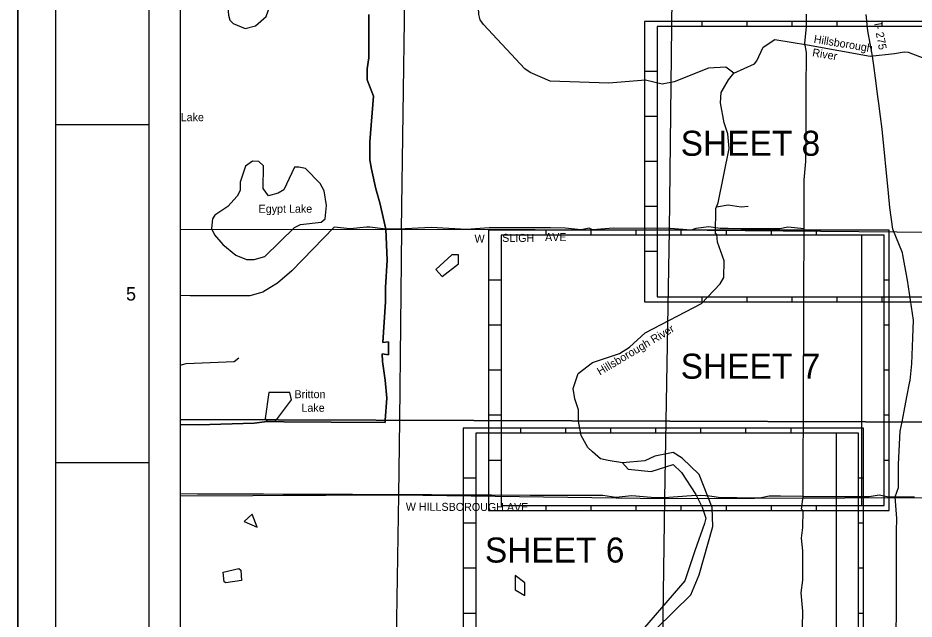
# Model space of a CAD drawing. Extents: x 492225 to 553725, y 1303773 to 1347273.
# Drawn here: x 492225 to 510130, y 1329150 to 1341161 of the extents above; entities that cross this region are included whole.
import ezdxf

# ---------------------------------------------------------------- set-up
doc = ezdxf.new("R2010")
doc.units = 0
for name, color, linetype in [('G-ANNO-TTLB', 7, 'Continuous'), ('Level 1', 7, 'Continuous'), ('Level 13', 7, 'Continuous'), ('Level 19', 7, 'Continuous'), ('Level 22', 7, 'Continuous'), ('Level 28', 7, 'Continuous'), ('Level 41', 7, 'Continuous'), ('Level 44', 7, 'Continuous'), ('Level 5', 7, 'Continuous'), ('Level 52', 7, 'Continuous'), ('Level 63', 7, 'Continuous'), ('Level 8', 7, 'Continuous')]:
    doc.layers.add(name, color=color, linetype=linetype)

msp = doc.modelspace()

# ---------------------------------------------------------------- linework, layer by layer
at = {"layer": 'G-ANNO-TTLB'}
for p, q in [((492975.069, 1346522.564), (492975.069, 1304522.564)), ((494850.069, 1305272.564), (494850.069, 1345772.564)), ((494850.069, 1339022.564), (492975.069, 1339022.564)), ((494850.069, 1332272.564), (492975.069, 1332272.564))]:
    msp.add_line(p, q, dxfattribs=at)
for points in [[(492225.069, 1303772.564), (553725.069, 1303772.564), (553725.069, 1347272.564), (492225.069, 1347272.564)], [(492225.069, 1303772.564), (553725.069, 1303772.564), (553725.069, 1347272.564), (492225.069, 1347272.564)], [(492225.069, 1347272.564), (553725.069, 1347272.564), (553725.069, 1303772.564), (492225.069, 1303772.564)]]:
    msp.add_lwpolyline(points, close=True, dxfattribs=at)
at = {"layer": 'Level 1'}
for p, q in [((499891.287, 1336934.999), (499965.224, 1342227.811)), ((505297.021, 1342191.301), (505239.221, 1336922.412)), ((505895.516, 1340991.129), (505895.516, 1341091.129)), ((506795.516, 1340991.129), (506795.516, 1341091.129)), ((507695.516, 1340991.129), (507695.516, 1341091.129)), ((508595.516, 1340991.129), (508595.516, 1341091.129)), ((509495.516, 1340991.129), (509495.516, 1341091.129)), ((504995.516, 1340091.129), (504745.516, 1340091.129)), ((504995.516, 1339191.129), (504745.516, 1339191.129)), ((504995.516, 1338291.129), (504745.516, 1338291.129)), ((504995.516, 1337391.129), (504745.516, 1337391.129)), ((499891.287, 1336934.999), (495463.793, 1336928.4312)), ((499891.287, 1336934.999), (499846.244, 1333124.585)), ((505239.221, 1336922.412), (499891.287, 1336934.999)), ((502779.174, 1336820.786), (502779.174, 1336920.786)), ((503679.174, 1336820.786), (503679.174, 1336920.786)), ((504579.174, 1336820.786), (504579.174, 1336920.786)), ((505239.221, 1336922.412), (505171.604, 1333105.552)), ((510580.913, 1336869.862), (505239.221, 1336922.412)), ((505479.174, 1336820.786), (505479.174, 1336920.786)), ((506379.174, 1336820.786), (506379.174, 1336920.786)), ((507279.174, 1336820.786), (507279.174, 1336920.786)), ((508179.174, 1336820.786), (508179.174, 1336920.786)), ((509079.174, 1336820.786), (509079.174, 1331420.786)), ((504995.516, 1336491.129), (504745.516, 1336491.129)), ((501879.174, 1335920.786), (501629.174, 1335920.786)), ((509629.174, 1335920.786), (509529.174, 1335920.786)), ((505895.516, 1335491.129), (505895.516, 1335591.129)), ((506795.516, 1335491.129), (506795.516, 1335591.129)), ((507695.516, 1335491.129), (507695.516, 1335591.129)), ((508595.516, 1335491.129), (508595.516, 1335591.129)), ((509495.516, 1335491.129), (509495.516, 1335591.129)), ((501879.174, 1335020.786), (501629.174, 1335020.786)), ((509629.174, 1335020.786), (509529.174, 1335020.786)), ((501879.174, 1334120.786), (501629.174, 1334120.786)), ((509629.174, 1334120.786), (509529.174, 1334120.786)), ((501879.174, 1333220.786), (501629.174, 1333220.786)), ((509629.174, 1333220.786), (509529.174, 1333220.786)), ((499846.244, 1333124.585), (499828.525, 1331625.601)), ((505171.604, 1333105.552), (505144.045, 1331549.672)), ((502271.149, 1332863.868), (502271.149, 1332963.868)), ((503171.149, 1332863.868), (503171.149, 1332963.868)), ((504071.149, 1332863.868), (504071.149, 1332963.868)), ((504971.149, 1332863.868), (504971.149, 1332963.868)), ((505871.149, 1332863.868), (505871.149, 1332963.868)), ((506771.149, 1332863.868), (506771.149, 1332963.868)), ((507671.149, 1332863.868), (507671.149, 1332963.868)), ((508571.149, 1332863.868), (508571.149, 1327463.868)), ((501879.174, 1332320.786), (501629.174, 1332320.786)), ((509629.174, 1332320.786), (509529.174, 1332320.786)), ((501371.149, 1331963.868), (501121.149, 1331963.868)), ((509121.149, 1331963.868), (509021.149, 1331963.868)), ((499828.525, 1331625.601), (495463.793, 1331605.0937)), ((499828.525, 1331625.601), (499738.271, 1326200.768)), ((505144.045, 1331549.672), (499828.525, 1331625.601)), ((502779.174, 1331320.786), (502779.174, 1331420.786)), ((503679.174, 1331320.786), (503679.174, 1331420.786)), ((504579.174, 1331320.786), (504579.174, 1331420.786)), ((505144.045, 1331549.672), (505073.326, 1326292.17)), ((510570.569, 1331572.735), (505144.045, 1331549.672)), ((505479.174, 1331320.786), (505479.174, 1331420.786)), ((506379.174, 1331320.786), (506379.174, 1331420.786)), ((507279.174, 1331320.786), (507279.174, 1331420.786)), ((508179.174, 1331320.786), (508179.174, 1331420.786)), ((501371.149, 1331063.868), (501121.149, 1331063.868)), ((509121.149, 1331063.868), (509021.149, 1331063.868)), ((501371.149, 1330163.868), (501121.149, 1330163.868)), ((509121.149, 1330163.868), (509021.149, 1330163.868)), ((501371.149, 1329263.868), (501121.149, 1329263.868)), ((509121.149, 1329263.868), (509021.149, 1329263.868))]:
    msp.add_line(p, q, dxfattribs=at)
for points in [[(504745.516, 1335491.129), (512745.516, 1335491.129), (512745.516, 1341091.129), (504745.516, 1341091.129)], [(504995.516, 1335591.129), (512645.516, 1335591.129), (512645.516, 1340991.129), (504995.516, 1340991.129)], [(501629.174, 1331320.786), (509629.174, 1331320.786), (509629.174, 1336920.786), (501629.174, 1336920.786)], [(501879.174, 1331420.786), (509529.174, 1331420.786), (509529.174, 1336820.786), (501879.174, 1336820.786)], [(501121.149, 1327363.868), (509121.149, 1327363.868), (509121.149, 1332963.868), (501121.149, 1332963.868)], [(501371.149, 1327463.868), (509021.149, 1327463.868), (509021.149, 1332863.868), (501371.149, 1332863.868)]]:
    msp.add_lwpolyline(points, close=True, dxfattribs=at)
at = {"layer": 'Level 13'}
for p, q in [((507980.347, 1340980.133), (507981.305, 1341234.618)), ((509206.094, 1340902.833), (509175.053, 1341230.149)), ((507946.849, 1340653.059), (507980.347, 1340980.133)), ((509300.983, 1340393.502), (509206.094, 1340902.833)), ((507978.428, 1340471.163), (507946.849, 1340653.059)), ((507977.332, 1340180.322), (507978.428, 1340471.163)), ((509324.502, 1340211.636), (509300.983, 1340393.502)), ((507976.647, 1339998.546), (507977.332, 1340180.322)), ((509357.429, 1339957.025), (509324.502, 1340211.636)), ((507976.236, 1339889.482), (507976.647, 1339998.546)), ((507975.139, 1339598.641), (507976.236, 1339889.482)), ((509404.469, 1339593.295), (509357.429, 1339957.025)), ((507973.906, 1339271.444), (507975.139, 1339598.641)), ((509423.285, 1339447.803), (509404.469, 1339593.295)), ((509456.214, 1339193.191), (509423.285, 1339447.803)), ((507973.239, 1339094.396), (507973.906, 1339271.444)), ((509489.142, 1338938.58), (509456.214, 1339193.191)), ((507971.303, 1338580.699), (507972.673, 1338944.249)), ((507972.673, 1338944.249), (507973.239, 1339094.396)), ((509616.345, 1337660.211), (509489.142, 1338938.58)), ((507970.207, 1338289.858), (507971.303, 1338580.699)), ((507936.571, 1337926.43), (507970.207, 1338289.858)), ((507935.338, 1337599.234), (507936.571, 1337926.43)), ((507932.871, 1336944.844), (507935.338, 1337599.234)), ((509644.644, 1337374.715), (509616.345, 1337660.211)), ((509707.552, 1336938.216), (509644.644, 1337374.715)), ((507932.049, 1336726.713), (507932.871, 1336944.844)), ((509899.396, 1336464.883), (509707.552, 1336938.216)), ((507931.501, 1336581.294), (507932.049, 1336726.713)), ((507930.679, 1336363.164), (507931.09, 1336472.229)), ((507931.09, 1336472.229), (507931.501, 1336581.294)), ((509906.037, 1336428.503), (509899.396, 1336464.883)), ((509994.306, 1335955.554), (509906.037, 1336428.503)), ((507929.994, 1336181.389), (507930.268, 1336254.099)), ((507930.268, 1336254.099), (507930.679, 1336363.164)), ((507929.173, 1335963.259), (507929.994, 1336181.389)), ((507928.624, 1335817.839), (507929.173, 1335963.259)), ((509999.656, 1335919.179), (509994.306, 1335955.554)), ((510079.331, 1335390.639), (509999.656, 1335919.179)), ((507927.939, 1335636.064), (507928.624, 1335817.839)), ((507927.254, 1335454.288), (507927.939, 1335636.064)), ((507926.158, 1335163.449), (507927.254, 1335454.288)), ((510120.272, 1335118.913), (510079.331, 1335390.639)), ((507925.063, 1334872.609), (507926.158, 1335163.449)), ((510106.072, 1334770.68), (510120.272, 1335118.913)), ((507923.966, 1334581.769), (507925.063, 1334872.609)), ((510084.763, 1334246.513), (510106.072, 1334770.68)), ((507922.734, 1334254.574), (507923.966, 1334581.769)), ((507921.774, 1334000.089), (507922.734, 1334254.574)), ((510051.279, 1333919.438), (510084.763, 1334246.513)), ((507920.405, 1333636.54), (507921.774, 1334000.089)), ((510047.331, 1333899.094), (510051.279, 1333919.438)), ((509985.524, 1333592.483), (510047.331, 1333899.094)), ((507919.172, 1333309.344), (507920.405, 1333636.54)), ((509930.23, 1333301.843), (509985.524, 1333592.483)), ((507918.368, 1333095.734), (507919.172, 1333309.344)), ((509889.504, 1333088.689), (509930.23, 1333301.843)), ((507917.803, 1332945.794), (507918.368, 1333095.734)), ((509853.878, 1332902.216), (509889.504, 1333088.689)), ((507916.435, 1332582.242), (507917.803, 1332945.794)), ((509819.175, 1332247.941), (509853.878, 1332902.216)), ((507915.339, 1332291.399), (507916.435, 1332582.242)), ((507914.109, 1331964.203), (507915.339, 1332291.399)), ((509817.419, 1331775.323), (509819.175, 1332247.941)), ((507912.74, 1331600.65), (507914.109, 1331964.203)), ((509752.202, 1331593.787), (509817.419, 1331775.323)), ((495810.994, 1331647.949), (495463.793, 1331649.3655)), ((496069.164, 1331646.901), (495810.994, 1331647.949)), ((496327.336, 1331645.855), (496069.164, 1331646.901)), ((496585.507, 1331644.811), (496327.336, 1331645.855)), ((496714.592, 1331644.288), (496585.507, 1331644.811)), ((497134.12, 1331642.597), (496714.592, 1331644.288)), ((497521.376, 1331641.038), (497134.12, 1331642.597)), ((497747.276, 1331640.132), (497521.376, 1331641.038)), ((498005.446, 1331639.096), (497747.276, 1331640.132)), ((498231.346, 1331638.192), (498005.446, 1331639.096)), ((498457.245, 1331637.289), (498231.346, 1331638.192)), ((498909.044, 1331635.486), (498457.245, 1331637.289)), ((499360.843, 1331633.689), (498909.044, 1331635.486)), ((499812.642, 1331631.898), (499360.843, 1331633.689)), ((500490.34, 1331629.219), (499812.642, 1331631.898)), ((501168.038, 1331626.553), (500490.34, 1331629.219)), ((501684.379, 1331624.528), (501168.038, 1331626.553)), ((502458.891, 1331621.506), (501684.379, 1331624.528)), ((503007.504, 1331619.373), (502458.891, 1331621.506)), ((503297.945, 1331618.248), (503007.504, 1331619.373)), ((503588.387, 1331617.124), (503297.945, 1331618.248)), ((503911.1, 1331615.879), (503588.387, 1331617.124)), ((504169.13, 1331578.528), (503911.1, 1331615.879)), ((504491.984, 1331613.643), (504169.13, 1331578.528)), ((504879.099, 1331575.802), (504491.984, 1331613.643)), ((505686.021, 1331609.073), (505137.27, 1331574.813)), ((505859.999, 1331617.864), (505686.021, 1331609.073)), ((505960.667, 1331612.391), (505859.999, 1331617.864)), ((506041.005, 1331607.723), (505960.667, 1331612.391)), ((506266.766, 1331570.509), (506041.005, 1331607.723)), ((507235.043, 1331603.2), (507041.278, 1331567.576)), ((507460.942, 1331602.348), (507235.043, 1331603.2)), ((507912.74, 1331600.65), (507460.942, 1331602.348)), ((507879.51, 1331346.284), (507912.74, 1331600.65)), ((507912.74, 1331600.65), (508235.453, 1331599.439)), ((508235.453, 1331599.439), (508558.165, 1331598.232)), ((508558.165, 1331598.232), (508880.879, 1331597.026)), ((508880.879, 1331597.026), (509235.862, 1331595.704)), ((509235.862, 1331595.704), (509429.625, 1331631.339)), ((509429.625, 1331631.339), (509623.117, 1331594.265)), ((509623.117, 1331594.265), (509752.202, 1331593.787)), ((509752.202, 1331593.787), (509957.453, 1331594.479)), ((509782.852, 1331157.404), (509752.202, 1331593.787)), ((509957.453, 1331594.479), (510139.457, 1331592.353)), ((505137.27, 1331574.813), (504879.099, 1331575.802)), ((506589.479, 1331569.285), (506266.766, 1331570.509)), ((507041.278, 1331567.576), (506589.479, 1331569.285)), ((507911.645, 1331309.808), (507879.51, 1331346.284)), ((507910.414, 1330982.611), (507911.645, 1331309.808)), ((509781.906, 1330902.917), (509782.852, 1331157.404)), ((507877.32, 1330764.601), (507910.414, 1330982.611)), ((509777.719, 1329775.906), (509781.906, 1330902.917)), ((507908.635, 1330509.993), (507877.32, 1330764.601)), ((507907.951, 1330328.217), (507908.635, 1330509.993)), ((507907.54, 1330219.151), (507907.951, 1330328.217)), ((507906.446, 1329928.309), (507907.54, 1330219.151)), ((507873.216, 1329673.944), (507906.446, 1329928.309)), ((507904.12, 1329310.271), (507873.216, 1329673.944)), ((509776.638, 1329485.064), (509777.719, 1329775.906)), ((509775.693, 1329230.578), (509776.638, 1329485.064)), ((507902.889, 1328983.074), (507904.12, 1329310.271)), ((509774.612, 1328939.736), (509775.693, 1329230.578))]:
    msp.add_line(p, q, dxfattribs=at)
at = {"layer": 'Level 22'}
for p, q in [((498543.184, 1336981.246), (497696.845, 1336109.19)), ((498865.709, 1336943.603), (498543.184, 1336981.246)), ((499188.524, 1336978.673), (498865.709, 1336943.603)), ((499253.058, 1336978.416), (499188.524, 1336978.673)), ((499575.583, 1336940.778), (499253.058, 1336978.416)), ((500479.204, 1336973.558), (499833.719, 1336939.754)), ((501188.934, 1336934.407), (500479.204, 1336973.558)), ((501640.815, 1336968.989), (501188.934, 1336934.407)), ((502092.552, 1336967.223), (501640.815, 1336968.989)), ((502576.558, 1336965.335), (502092.552, 1336967.223)), ((502866.96, 1336964.206), (502576.558, 1336965.335)), ((503157.363, 1336963.078), (502866.96, 1336964.206)), ((503479.891, 1336925.473), (503157.363, 1336963.078)), ((503641.368, 1336961.203), (503479.891, 1336925.473)), ((503705.76, 1336924.599), (503641.368, 1336961.203)), ((504125.372, 1336959.335), (503705.76, 1336924.599)), ((505254.715, 1336954.998), (504125.372, 1336959.335)), ((505674.047, 1336917.041), (505254.715, 1336954.998)), ((505770.987, 1336953.027), (505674.047, 1336917.041)), ((506029.261, 1336988.398), (505770.987, 1336953.027)), ((506254.991, 1336951.185), (506029.261, 1336988.398)), ((506416.325, 1336950.572), (506254.991, 1336951.185)), ((507610.339, 1336982.413), (507448.867, 1336946.666)), ((507932.871, 1336944.844), (507610.339, 1336982.413)), ((499833.719, 1336939.754), (499575.583, 1336940.778)), ((506674.46, 1336949.593), (506416.325, 1336950.572)), ((506964.864, 1336948.493), (506674.46, 1336949.593)), ((507222.999, 1336947.518), (506964.864, 1336948.493)), ((507448.867, 1336946.666), (507222.999, 1336947.518)), ((497696.845, 1336109.19), (497409.293, 1335858.764)), ((497256.619, 1335767.763), (497118.148, 1335678.158)), ((497409.293, 1335858.764), (497256.619, 1335767.763)), ((495665.787, 1335611.328), (495463.793, 1335612.1507)), ((496859.709, 1335606.488), (495665.787, 1335611.328)), ((497118.148, 1335678.158), (496859.709, 1335606.488))]:
    msp.add_line(p, q, dxfattribs=at)
at = {"layer": 'Level 5'}
for p, q in [((506183.937, 1337387.318), (506418.124, 1337423.187)), ((506418.124, 1337423.187), (506676.119, 1337385.853)), ((506676.119, 1337385.853), (506814.274, 1337399.872)), ((497178.728, 1333134.119), (497204.532, 1333096.55)), ((497204.532, 1333096.55), (497365.883, 1333095.9)), ((497365.883, 1333095.9), (497393.819, 1333133.351)), ((503424.827, 1333104.882), (503424.848, 1333111.794))]:
    msp.add_line(p, q, dxfattribs=at)
for points in [[(506529.841, 1340054.49), (506371.861, 1340179.978), (506021.752, 1340156.035), (505337.504, 1339883.09), (505095.654, 1339833.828), (504762.534, 1339918.205), (504028.936, 1339853.778), (502862.259, 1339898.998), (502462.729, 1340066.903), (502354.62, 1340142.243), (501523.911, 1341028.223), (501457.531, 1341120.112), (501432.861, 1341228.522), (501401.741, 1341953.69), (501294.071, 1342170.718), (501204.146, 1342305.219), (501204.6902, 1342691.84)], [(506529.841, 1340054.49), (506938.8, 1340244.913), (506988.99, 1340303.103), (507114.84, 1340577.733), (507348.65, 1340727.055), (507998.429, 1340625.051), (509255.085, 1340394.675), (509738.85, 1340450.259), (509933.283, 1340481.139), (510009.667, 1340474.192), (511388.39, 1339947.934)], [(506335.12, 1339063.282), (506261.321, 1339463.55), (506278.641, 1339671.859), (506421.071, 1339921.46), (506529.841, 1340054.49)], [(506213.499, 1337463.477), (506433.559, 1338554.605), (506409.449, 1338846.373), (506335.12, 1339063.282)], [(503424.848, 1333111.794), (503425.507, 1333329.882), (503351.177, 1333546.82), (503318.467, 1333755.279), (503419.397, 1334054.999), (503703.466, 1334279.142), (504245.714, 1334452.517), (504446.133, 1334585.248), (504755.382, 1334867.651), (505882.309, 1335455.95), (506258.557, 1335846.493), (506325.617, 1335971.303), (506334.958, 1336304.662), (506202.769, 1336680.109), (506186.599, 1336838.498), (506161.629, 1336846.918), (506171.499, 1337355.277), (506213.499, 1337463.477)], [(501024.876, 1336244.293), (501025.593, 1336426.069), (500896.523, 1336426.577), (500572.699, 1336137.007), (500701.194, 1335991.078), (501024.876, 1336244.293)], [(495463.793, 1334221.8478), (495585.848, 1334253.997), (496544.384, 1334292.707), (496636.304, 1334367.458)], [(497393.819, 1333133.351), (497690.341, 1333530.866), (497658.656, 1333676.415), (497239.15, 1333678.103), (497163.467, 1333156.339), (497178.728, 1333134.119)], [(504301.574, 1332273.468), (504018.315, 1332315.995), (503862.916, 1332353.793), (503702.167, 1332491.943), (503610.717, 1332575.592), (503478.107, 1332817.682), (503424.827, 1333104.882)], [(504975.097, 1328954.432), (505668.853, 1329635.782), (505836.731, 1330035.316), (506106.309, 1331001.313), (506099.108, 1331376.374), (505834.348, 1332035.583), (505493.639, 1332361.612), (505318.959, 1332478.83), (504952.031, 1332404.906), (504751.732, 1332313.813), (504301.574, 1332273.468)], [(504301.574, 1332273.468), (504417.874, 1332148.129), (504876.102, 1332096.763), (505318.22, 1332237.119), (505484.439, 1332078.29), (505766.489, 1331635.722), (505896.408, 1331384.399), (505967.061, 1331169.113), (505942.981, 1331056.257), (505746.471, 1330510.657), (505552.993, 1329911.152), (504490.919, 1328689.166)], [(496906.604, 1331243.598), (496744.657, 1331098.828), (497002.39, 1330988.721), (496906.604, 1331243.598)], [(502354.27, 1329622.343), (502355.264, 1329876.829), (502162.195, 1330023.006), (502161.058, 1329732.163), (502354.27, 1329622.343)]]:
    msp.add_lwpolyline(points, dxfattribs=at)
for points in [[(496764.85, 1340951.092), (496973.36, 1341000.473), (497182.289, 1341191.525), (497274.709, 1341432.925), (497300.309, 1341624.535), (497250.599, 1341724.705), (497159.239, 1341824.984), (496934.559, 1341942.342), (496751.199, 1341942.91), (496651.099, 1341909.899), (496475.389, 1341685.388), (496408.18, 1341510.568), (496432.291, 1341218.798), (496457.001, 1341118.728), (496523.471, 1341051.839), (496764.85, 1340951.092)], [(496942.369, 1336333.388), (497159.218, 1336391.081), (497752.755, 1336972.636), (497869.584, 1337030.627), (498286.474, 1337079.361), (498361.693, 1337145.802), (498387.493, 1337412.421), (498346.702, 1337704.25), (498263.832, 1337854.509), (497973.073, 1338155.446), (497839.783, 1338180.835), (497748.133, 1338181.124), (497538.374, 1337723.373), (497421.475, 1337657.082), (497229.635, 1337607.64), (497121.726, 1337749.648), (497131.454, 1338208.028), (497040.045, 1338291.637), (496915.055, 1338300.356), (496773.066, 1338200.785), (496663.737, 1337876.094), (496663.237, 1337709.394), (496604.538, 1337601.224), (496420.559, 1337393.423), (496161.679, 1337219.22), (496111.43, 1337144.359), (496094.17, 1336952.719), (496152.13, 1336827.53), (496318.23, 1336635.322), (496575.92, 1336417.855), (496792.349, 1336333.857), (496942.369, 1336333.388)], [(496376.892, 1329871.764), (496343.642, 1329896.854), (496327.531, 1330088.574), (496636.12, 1330162.678), (496677.71, 1330129.218), (496693.75, 1329920.828), (496376.892, 1329871.764)]]:
    msp.add_lwpolyline(points, close=True, dxfattribs=at)
at = {"layer": 'Level 52'}
msp.add_lwpolyline([(518939.5614, 1342691.8404), (495463.7934, 1342691.8404), (495463.7934, 1307817.676), (518939.5614, 1307817.676)], close=True, dxfattribs=at)
at = {"layer": 'Level 63'}
for points in [[(518939.561, 1333056.3431), (495463.793, 1333140.2488)], [(495463.793, 1333140.2488), (518939.561, 1333056.3431)]]:
    msp.add_lwpolyline(points, dxfattribs=at)
at = {"layer": 'Level 8'}
for points in [[(499562.909, 1333125.598), (499594.393, 1333560.09), (499563.393, 1333923.089), (499512.393, 1334299.088), (499502.392, 1334450.088), (499630.392, 1334432.089), (499630.392, 1334577.088), (499631.392, 1334686.088), (499513.392, 1334677.088), (499569.391, 1335486.086), (499571.39, 1335777.086), (499605.39, 1336323.085), (499575.389, 1336941.083), (499457.389, 1337463.082), (499376.389, 1337743.08), (499290.389, 1338142.078), (499258.389, 1338323.078), (499259.389, 1338687.078), (499328.387, 1339596.077), (499200.387, 1339923.074), (499201.387, 1340141.074), (499234.386, 1340360.074), (499235.386, 1340578.074), (499236.386, 1340832.073), (499236.386, 1340893.073), (499237.385, 1341087.073), (499237.385, 1341232.073)], [(499237.385, 1341232.073), (499237.385, 1341087.073), (499236.386, 1340893.073), (499236.386, 1340832.073), (499235.386, 1340578.074), (499234.386, 1340360.074), (499201.387, 1340141.074), (499200.387, 1339923.074), (499328.387, 1339596.077), (499259.389, 1338687.078), (499258.389, 1338323.078), (499290.389, 1338142.078), (499376.389, 1337743.08), (499457.389, 1337463.082), (499575.389, 1336941.083), (499605.39, 1336323.085), (499571.39, 1335777.086), (499569.391, 1335486.086), (499513.392, 1334677.088), (499631.392, 1334686.088), (499630.392, 1334577.088), (499630.392, 1334432.089), (499502.392, 1334450.088), (499512.393, 1334299.088), (499563.393, 1333923.089), (499594.393, 1333560.09), (499562.909, 1333125.598)], [(499562.909, 1333125.598), (499559.394, 1333077.09), (498485.398, 1333081.079), (497535.402, 1333091.068), (497365.403, 1333096.067), (497204.404, 1333096.065), (496946.404, 1333061.062), (495836.409, 1333028.05), (495463.793, 1333034.2908)], [(495463.793, 1333034.2908), (495836.409, 1333028.05), (496946.404, 1333061.062), (497204.404, 1333096.065), (497365.403, 1333096.067)], [(497365.403, 1333096.067), (497535.402, 1333091.068), (498485.398, 1333081.079), (499559.394, 1333077.09), (499562.909, 1333125.598)]]:
    msp.add_lwpolyline(points, dxfattribs=at)

# ---------------------------------------------------------------- texts
at = {"layer": 'G-ANNO-TTLB'}
msp.add_text('5', height=267.507, dxfattribs=at).set_placement((494385.069, 1335514.064))
at = {"layer": 'Level 1'}
for s, p in [('SHEET 8', (505467.379, 1338405.907)), ('SHEET 7', (505467.379, 1333952.465)), ('SHEET 6', (501555.496, 1330278.879))]:
    msp.add_text(s, height=500, dxfattribs=at).set_placement(p)
at = {"layer": 'Level 19'}
for s, height, rotation, p in [('I- 275', 160, 280.55341389, (509329.278, 1341050.078)), ('W HILLSBOROUGH AVE', 159.999996, 359.77481668, (499974.579, 1331315.053))]:
    msp.add_text(s, height=height, rotation=rotation, dxfattribs=at).set_placement(p)
at = {"layer": 'Level 28'}
for s, p in [('W', (501347.808, 1336669.452)), ('SLIGH', (501899.941, 1336686.356)), ('AVE', (502756.487, 1336702.196))]:
    msp.add_text(s, height=160, rotation=359.77600001, dxfattribs=at).set_placement(p)
at = {"layer": 'Level 41'}
for s, height, rotation, p in [('Hillsborough', 159.999996, 350.63900005, (508117.263, 1340665.889)), ('River', 160, 350.63900005, (508087.097, 1340395.781)), ('Hillsborough River', 159.999156, 30.78017497, (503853.825, 1334013.3))]:
    msp.add_text(s, height=height, rotation=rotation, dxfattribs=at).set_placement(p)
for s, p in [('Egypt Lake', (497034.055, 1337268.542)), ('Britton', (497751.254, 1333563.188)), ('Lake', (497889.458, 1333292.006))]:
    msp.add_text(s, height=160, dxfattribs=at).set_placement(p)
at = {"layer": 'Level 44'}
msp.add_text('Lake', height=160, dxfattribs=at).set_placement((495477.004, 1339097.706))

doc.saveas('drawing.dxf')
